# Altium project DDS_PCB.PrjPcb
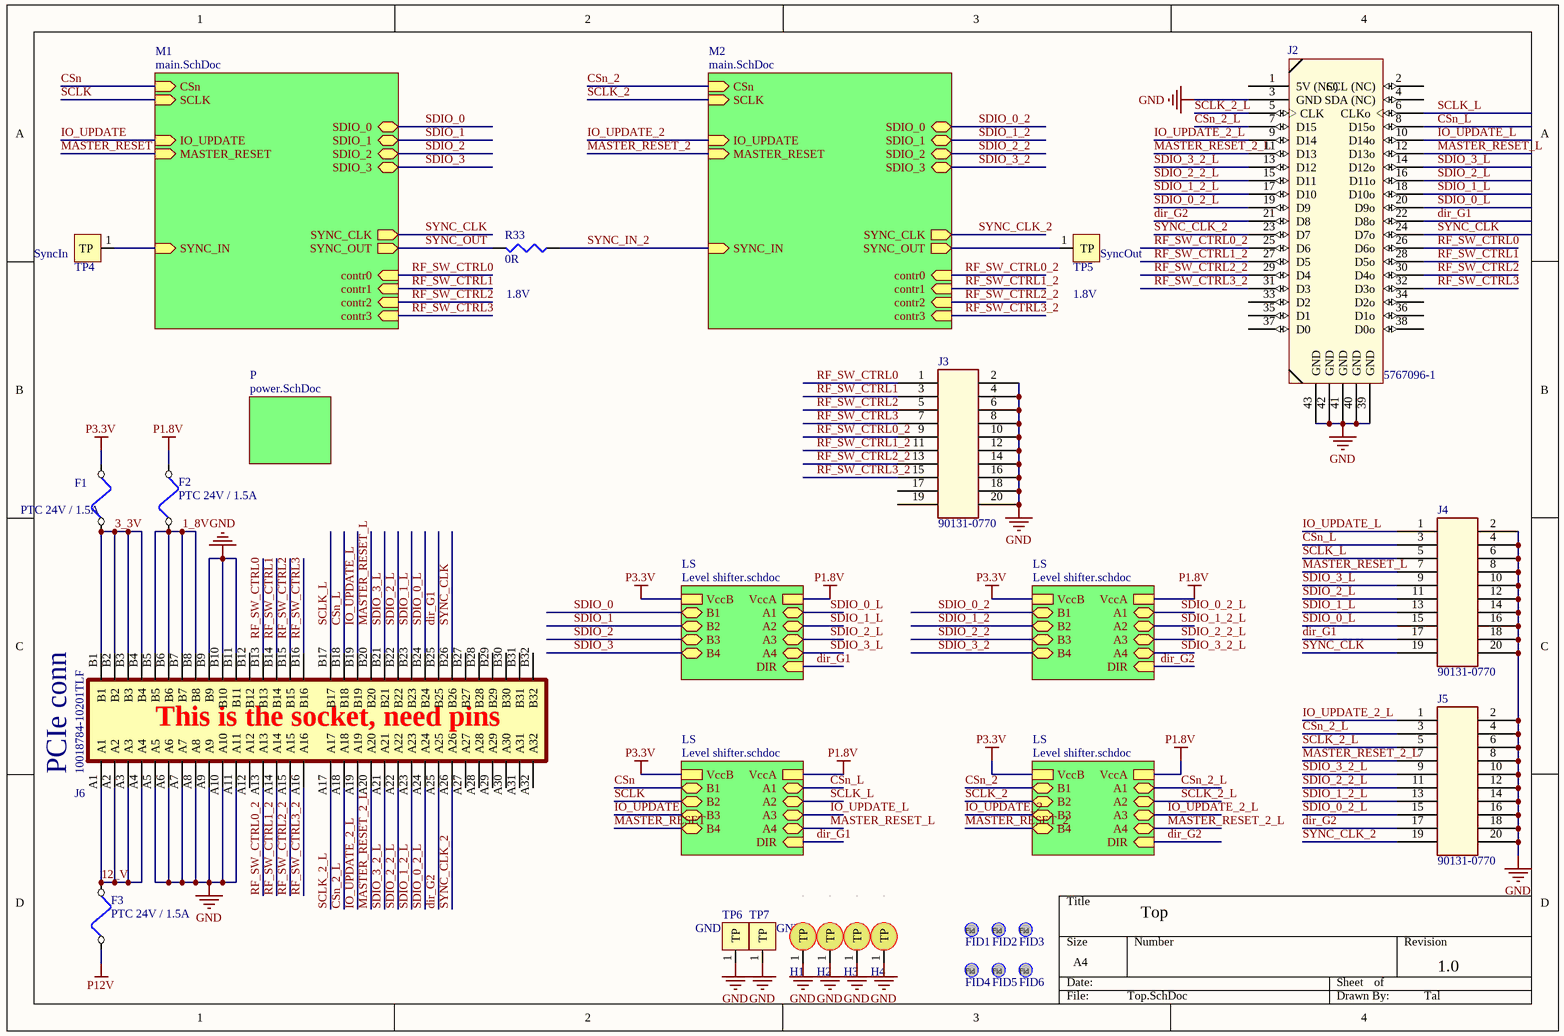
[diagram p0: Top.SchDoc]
6 sheets, 434 parts. Net scope: hierarchical (ports join the sheet entries above them; power ports are global).
Board file: DDS_PCB.PcbDoc
Sheets:
  Top.SchDoc
    M1 = main.SchDoc
      A0 = analog_channel.SchDoc
      A1 = analog_channel.SchDoc
      B0 = analog_channel3.SchDoc
      B1 = analog_channel3.SchDoc
    P = power.SchDoc
    M2 = main.SchDoc
      A0 = analog_channel.SchDoc
      A1 = analog_channel.SchDoc
      B0 = analog_channel3.SchDoc
      B1 = analog_channel3.SchDoc
    LS = Level Shifter.SchDoc
    LS = Level Shifter.SchDoc
    LS = Level Shifter.SchDoc
    LS = Level Shifter.SchDoc

## Sheet Top.SchDoc
size A4; SheetNumber: 1; SheetTotal: 6

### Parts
F1  PTC 24V / 1.5A  [1812_F]
F2  PTC 24V / 1.5A  [1812_F]
F3  PTC 24V / 1.5A  [1812_F]
FID1  Fiducial  [Fiducial]  (value not drawn)
FID2  Fiducial  [Fiducial]  (value not drawn)
FID3  Fiducial  [Fiducial]  (value not drawn)
FID4  Fiducial  [Fiducial]  (value not drawn)
FID5  Fiducial  [Fiducial]  (value not drawn)
FID6  Fiducial  [Fiducial]  (value not drawn)
H1  Hole 3mm  [hole 3mm]  (value not drawn)
H2  Hole 3mm  [hole 3mm]  (value not drawn)
H3  Hole 3mm  [hole 3mm]  (value not drawn)
H4  Hole 3mm  [hole 3mm]  (value not drawn)
J2  5767096-1  [MICTOR-38_PIN]
J3  90131-0770  [HEADER_10x2]
J4  90131-0770  [HEADER_10x2]
J5  90131-0770  [HEADER_10x2]
J6  10018784-10201TLF  [PCIE_8LANE_EDGE]
R33  0R  [R0402]
TP4  SyncIn  [TP_2x1.8]
TP5  SyncOut  [TP_2x1.8]
TP6  GND  [TP_2x1.8]
TP7  GND  [TP_2x1.8]

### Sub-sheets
LS = Level shifter.schdoc: A4 (bidir), B3 (bidir), A2 (bidir), B1 (bidir), B4 (bidir), A1 (bidir), B2 (bidir), A3 (bidir), VccA, VccB, DIR (in)
LS = Level shifter.schdoc: A4 (bidir), B3 (bidir), A2 (bidir), B1 (bidir), B4 (bidir), A1 (bidir), B2 (bidir), A3 (bidir), VccA, VccB, DIR (in)
LS = Level shifter.schdoc: A4 (bidir), B3 (bidir), A2 (bidir), B1 (bidir), B4 (bidir), A1 (bidir), B2 (bidir), A3 (bidir), VccA, VccB, DIR (in)
LS = Level shifter.schdoc: A4 (bidir), B3 (bidir), A2 (bidir), B1 (bidir), B4 (bidir), A1 (bidir), B2 (bidir), A3 (bidir), VccA, VccB, DIR (in)
M1 = main.SchDoc: SYNC_CLK (out), SYNC_OUT (out), SDIO_0 (bidir), SDIO_1 (bidir), SDIO_2 (bidir), SDIO_3 (bidir), CSn (in), IO_UPDATE (in), MASTER_RESET (in), SCLK (in), SYNC_IN (in), contr0 (in), contr1 (in), contr2 (in), contr3 (in)
M2 = main.SchDoc: SYNC_CLK (out), SYNC_OUT (out), SDIO_0 (bidir), SDIO_1 (bidir), SDIO_2 (bidir), SDIO_3 (bidir), CSn (in), IO_UPDATE (in), MASTER_RESET (in), SCLK (in), SYNC_IN (in), contr0 (in), contr1 (in), contr2 (in), contr3 (in)
P = power.SchDoc: no entries

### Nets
GND: H1.1(TP) H2.1(TP) H3.1(TP) H4.1(TP) J2.3(GND) J2.39(GND) J2.40(GND) J2.41(GND) J2.42(GND) J2.43(GND) J3.2 J3.4 J3.6 J3.8 J3.10 J3.12 J3.14 J3.16 J3.18 J3.20 J4.2 J4.4 J4.6 J4.8 J4.10 J4.12 J4.14 J4.16 J4.18 J4.20 J5.2 J5.4 J5.6 J5.8 J5.10 J5.12 J5.14 J5.16 J5.18 J5.20 J6.A5 J6.A6 J6.A7 J6.A8 J6.A9 J6.A10 J6.A11 J6.B9 J6.B10 J6.B11 TP6.1(TP) TP7.1(TP)
P1.8V: F2.2 ; sheet LS/VccA, sheet LS/VccA, sheet LS/VccA, sheet LS/VccA  [project net VccA]
P3.3V: F1.2 ; sheet LS/VccB, sheet LS/VccB, sheet LS/VccB, sheet LS/VccB  [project net VccB]
P12V: F3.1
1_8V: F2.1 J6.B5 J6.B6 J6.B7 J6.B8
3_3V: F1.1 J6.B1 J6.B2 J6.B3 J6.B4
12_V: F3.2 J6.A1 J6.A2 J6.A3 J6.A4
CSn: sheet M1/CSn, sheet LS/B1
CSn_2: sheet M2/CSn, sheet LS/B1
CSn_2_L: J2.7(D15) J5.3 J6.A18 ; sheet LS/A1
CSn_L: J2.8(D15o) J4.3 J6.B18 ; sheet LS/A1
dir_G1: J2.22(D8o) J4.17 J6.B25 ; sheet LS/DIR, sheet LS/DIR  [project net DIR]
dir_G2: J2.21(D8) J5.17 J6.A25 ; sheet LS/DIR, sheet LS/DIR  [project net DIR]
IO_UPDATE: sheet M1/IO_UPDATE, sheet LS/B3
IO_UPDATE_2: sheet M2/IO_UPDATE, sheet LS/B3
IO_UPDATE_2_L: J2.9(D14) J5.1 J6.A19 ; sheet LS/A3
IO_UPDATE_L: J2.10(D14o) J4.1 J6.B19 ; sheet LS/A3
MASTER_RESET: sheet M1/MASTER_RESET, sheet LS/B4
MASTER_RESET_2: sheet M2/MASTER_RESET, sheet LS/B4
MASTER_RESET_2_L: J2.11(D13) J5.7 J6.A20 ; sheet LS/A4
MASTER_RESET_L: J2.12(D13o) J4.7 J6.B20 ; sheet LS/A4
RF_SW_CTRL0: J2.26(D6o) J3.1 J6.B13 ; sheet M1/contr0  [project net contr0]
RF_SW_CTRL0_2: J2.25(D6) J3.9 J6.A13 ; sheet M2/contr0  [project net contr0]
RF_SW_CTRL1: J2.28(D5o) J3.3 J6.B14 ; sheet M1/contr1  [project net contr1]
RF_SW_CTRL1_2: J2.27(D5) J3.11 J6.A14 ; sheet M2/contr1  [project net contr1]
RF_SW_CTRL2: J2.30(D4o) J3.5 J6.B15 ; sheet M1/contr2  [project net contr2]
RF_SW_CTRL2_2: J2.29(D4) J3.13 J6.A15 ; sheet M2/contr2  [project net contr2]
RF_SW_CTRL3: J2.32(D3o) J3.7 J6.B16 ; sheet M1/contr3  [project net contr3]
RF_SW_CTRL3_2: J2.31(D3) J3.15 J6.A16 ; sheet M2/contr3  [project net contr3]
SCLK: sheet M1/SCLK, sheet LS/B2
SCLK_2: sheet M2/SCLK, sheet LS/B2
SCLK_2_L: J2.5(CLK) J5.5 J6.A17 ; sheet LS/A2
SCLK_L: J2.6(CLKo) J4.5 J6.B17 ; sheet LS/A2
SDIO_0: sheet M1/SDIO_0, sheet LS/B1
SDIO_0_2: sheet M2/SDIO_0, sheet LS/B1
SDIO_0_2_L: J2.19(D9) J5.15 J6.A24 ; sheet LS/A1
SDIO_0_L: J2.20(D9o) J4.15 J6.B24 ; sheet LS/A1
SDIO_1: sheet M1/SDIO_1, sheet LS/B2
SDIO_1_2: sheet M2/SDIO_1, sheet LS/B2
SDIO_1_2_L: J2.17(D10) J5.13 J6.A23 ; sheet LS/A2
SDIO_1_L: J2.18(D10o) J4.13 J6.B23 ; sheet LS/A2
SDIO_2: sheet M1/SDIO_2, sheet LS/B3
SDIO_2_2: sheet M2/SDIO_2, sheet LS/B3
SDIO_2_2_L: J2.15(D11) J5.11 J6.A22 ; sheet LS/A3
SDIO_2_L: J2.16(D11o) J4.11 J6.B22 ; sheet LS/A3
SDIO_3: sheet M1/SDIO_3, sheet LS/B4
SDIO_3_2: sheet M2/SDIO_3, sheet LS/B4
SDIO_3_2_L: J2.13(D12) J5.9 J6.A21 ; sheet LS/A4
SDIO_3_L: J2.14(D12o) J4.9 J6.B21 ; sheet LS/A4
SYNC_CLK: J2.24(D7o) J4.19 J6.B26 ; sheet M1/SYNC_CLK
SYNC_CLK_2: J2.23(D7) J5.19 J6.A26 ; sheet M2/SYNC_CLK
SYNC_IN: TP4.1(TP) ; sheet M1/SYNC_IN
SYNC_IN_2: R33.1 ; sheet M2/SYNC_IN
SYNC_OUT: TP5.1(TP) ; sheet M2/SYNC_OUT
SYNC_OUT: R33.2 ; sheet M1/SYNC_OUT  [a separate net that carries the same name]

Not connected (* = marked no-connect by the designer): J2 1(5V_(NC)) 2(SCL_(NC)) 4(SDA_(NC)) 33(D2) 34(D2o) 35(D1) 36(D1o) 37(D0) 38(D0o); J3 17 19; J6 A12 A27 A28 A29 A30 A31 A32 B12 B27 B28 B29 B30 B31 B32

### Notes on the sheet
- (near R33) 1.8V
- (near TP5) 1.8V
- (near J6) PCIe conn
- (near J6) This is the socket, need pins
- Top
- 1.0
- Tal

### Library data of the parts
F1-F3 = 1812L150/24MR: FUSE PTC 24V 1.5A POLYFUSE 1812; Manufacturer: Littelfuse Inc; LANDA P/N: EFS-000011
FID1-FID6 = Fiducial: Assembly: NA
J2 = 5767096-1: CONN MICTOR 38POS .025 VERT SMD; Manufacturer: TE Connectivity; LANDA P/N: ECN-000060
J3-J5 = 90131-0770: CONN HEADER 20 TH; Manufacturer: Molex Connector Corporation; LANDA P/N: ECN-000005
J6 = 10018784-10201TLF: 64 Position Female Connector PCI Expressâ„¢ Gold 0.039 _1.00mm_ Black; MF: Amphenol ICC
R33 = RES 100 OHM 1/10W 1% 0402 SMD: RES 0 OHM 1/10W 1% 0402 SMD; Manufacturer Part Number: ERJ-2RKF1000X; Manufacturer: Panasonic Electronic Components; LANDA P/N: ERS-000079; Assembly: N.C
TP4-TP6 = TP mini_2: TP PC MINIATURE SMT; Manufacturer: Keystone Electronics; Manufacturer Part Number: 5015; Assembly: N.A; LANDA P/N: ECN-000032
TP7 = TP mini_1: TP PC MINIATURE SMT; Manufacturer: Keystone Electronics; Manufacturer Part Number: 5015; Assembly: N.A; LANDA P/N: ECN-000032

## Sheet main.SchDoc
size A4; SheetNumber: 2; SheetTotal: 6; SPICEModelCacheQOCYWOGJ: <root> / <DocumentId>QOCYWOGJ</DocumentId> / </root>
Used 2 times, as channels M1, M2. Parts and nets are listed once, with the designators drawn on the sheet.
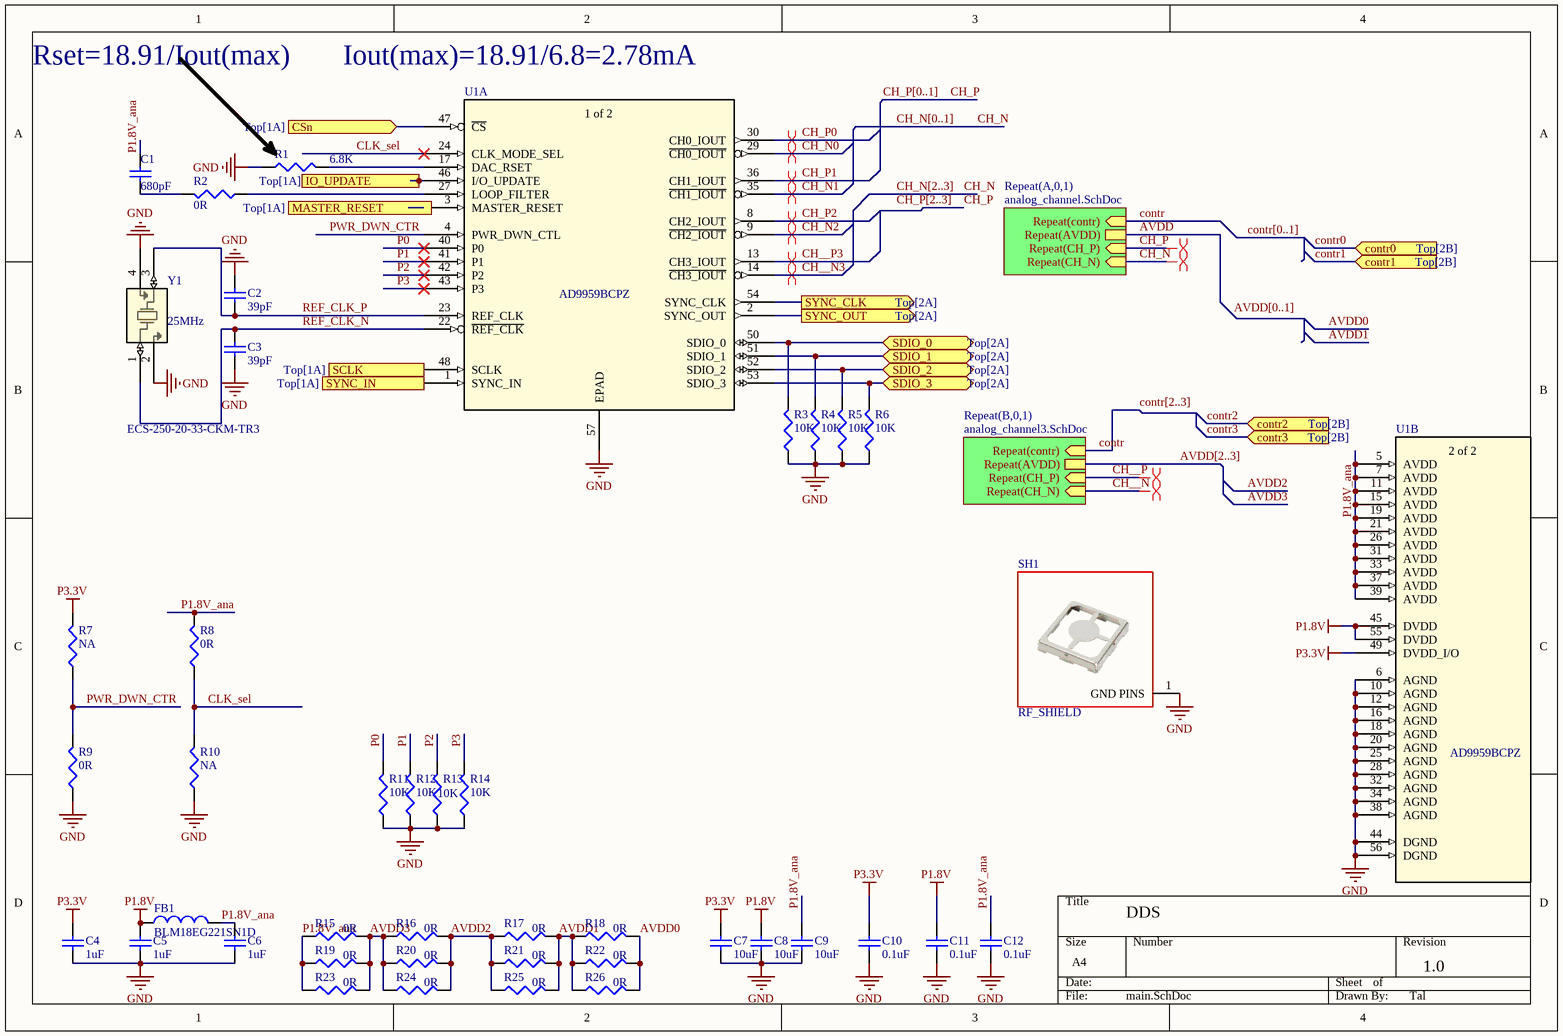
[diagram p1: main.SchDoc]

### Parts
C1  Capacitance: 680pF  [C0402]  (hidden comment: 680pF 50V)
C2  Capacitance: 39pF  [C0402]  (hidden comment: 39pF 50V)
C3  Capacitance: 39pF  [C0402]  (hidden comment: 39pF 50V)
C4  Capacitance: 1uF  [C0402]  (hidden comment: 1uF 25V)
C5  Capacitance: 1uF  [C0402]  (hidden comment: 1uF 25V)
C6  Capacitance: 1uF  [C0402]  (hidden comment: 1uF 25V)
C7  Capacitance: 10uF  [C0402]  (hidden comment: 10uF 10V)
C8  Capacitance: 10uF  [C0402]  (hidden comment: 10uF 10V)
C9  Capacitance: 10uF  [C0402]  (hidden comment: 10uF 10V)
C10  Capacitance: 0.1uF  [C0402]  (hidden comment: 0.1uF 50V)
C11  Capacitance: 0.1uF  [C0402]  (hidden comment: 0.1uF 50V)
C12  Capacitance: 0.1uF  [C0402]  (hidden comment: 0.1uF 50V)
FB1  BLM18EG221SN1D  [fb0603]
R1  6.8K  [R0402]
R2  0R  [R0402]
R3  10K  [R0402]
R4  10K  [R0402]
R5  10K  [R0402]
R6  10K  [R0402]
R7  NA  [R0402]
R8  0R  [R0402]
R9  0R  [R0402]
R10  NA  [R0402]
R11  10K  [R0402]
R12  10K  [R0402]
R13  10K  [R0402]
R14  10K  [R0402]
R15  0R  [R0805]
R16  0R  [R0805]
R17  0R  [R0805]
R18  0R  [R0805]
R19  0R  [R0805]
R20  0R  [R0805]
R21  0R  [R0805]
R22  0R  [R0805]
R23  0R  [R0805]
R24  0R  [R0805]
R25  0R  [R0805]
R26  0R  [R0805]
SH1  RF_SHIELD  [SMS201F]
U1  AD9959BCPZ  [CP_56_1_ADI]  (parts A,B of 2)
Y1  ECS-250-20-33-CKM-TR3  [SMD4_ECX-32_3p2x2p5_ECS]

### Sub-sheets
Repeat(A,0,1) = analog_channel.SchDoc: Repeat(contr) (in), Repeat(AVDD), Repeat(CH_P) (in), Repeat(CH_N) (in)
Repeat(B,0,1) = analog_channel3.SchDoc: Repeat(contr) (in), Repeat(AVDD), Repeat(CH_P) (in), Repeat(CH_N) (in)

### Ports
contr0 (in, see Top[2B]), contr1 (in, see Top[2B]), contr2 (in, see Top[2B]), contr3 (in, see Top[2B]), CSn (in, see Top[1A]), IO_UPDATE (in, see Top[1A]), MASTER_RESET (in, see Top[1A]), SCLK (in, see Top[1A]), SDIO_0 (bidir, see Top[2A]), SDIO_1 (bidir, see Top[2A]), SDIO_2 (bidir, see Top[2A]), SDIO_3 (bidir, see Top[2A]), SYNC_CLK (out, see Top[2A]), SYNC_IN (in, see Top[1A]), SYNC_OUT (out, see Top[2A])

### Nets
GND: C2.2 C3.1 C4.1 C5.1 C6.1 C7.1 C8.1 C9.1 C10.1 C11.1 C12.1 R1.1 R3.1 R4.1 R5.1 R6.1 R9.1 R10.1 R11.1 R12.1 R13.1 R14.1 SH1.1(GND_PINS) U1.6(AGND) U1.10(AGND) U1.12(AGND) U1.16(AGND) U1.18(AGND) U1.20(AGND) U1.25(AGND) U1.28(AGND) U1.32(AGND) U1.34(AGND) U1.38(AGND) U1.44(DGND) U1.56(DGND) U1.57(EPAD) Y1.2 Y1.4
P1.8V: C5.2 C8.2 C11.2 FB1.1 U1.45(DVDD) U1.55(DVDD)
P3.3V: C4.2 C7.2 C10.2 R7.2 U1.49(DVDD_I/O)
AVDD0: R18.2 R22.2 R26.2
AVDD1: R17.2 R18.1 R21.2 R22.1 R25.2 R26.1
AVDD2: R16.2 R17.1 R20.2 R21.1 R24.2 R25.1
AVDD3: R15.2 R16.1 R19.2 R20.1 R23.2 R24.1
CH__N3: U1.14(~{CH3_IOUT})
CH__P3: U1.13(CH3_IOUT)
CH_N0: U1.29(~{CH0_IOUT})
CH_N1: U1.35(~{CH1_IOUT})
CH_N2: U1.9(~{CH2_IOUT})
CH_P0: U1.30(CH0_IOUT)
CH_P1: U1.36(CH1_IOUT)
CH_P2: U1.8(CH2_IOUT)
CLK_sel: R8.1 R10.2 U1.24(CLK_MODE_SEL)
contr: sheet Repeat(A,0,1)/Repeat(contr), sheet Repeat(B,0,1)/Repeat(contr)  [also labelled contr[2..3]]
CSn: U1.47(~{CS}) ; port CSn
IO_UPDATE: U1.46(I/O_UPDATE) ; port IO_UPDATE
P0: R11.2 U1.40(P0)
P1: R12.2 U1.41(P1)
P1.8V_ana: C1.1 C6.2 C9.2 C12.2 FB1.2 R8.2 R15.1 R19.1 R23.1 U1.5(AVDD) U1.7(AVDD) U1.11(AVDD) U1.15(AVDD) U1.19(AVDD) U1.21(AVDD) U1.26(AVDD) U1.31(AVDD) U1.33(AVDD) U1.37(AVDD) U1.39(AVDD)
P2: R13.2 U1.42(P2)
P3: R14.2 U1.43(P3)
PWR_DWN_CTR: R7.1 R9.2 U1.4(PWR_DWN_CTL)
REF_CLK_N: C3.2 U1.22(~{REF_CLK}) Y1.1
REF_CLK_P: C2.1 U1.23(REF_CLK) Y1.3
SCLK: U1.48(SCLK) ; port SCLK
SDIO_0: R3.2 U1.50(SDIO_0) ; port SDIO_0
SDIO_1: R4.2 U1.51(SDIO_1) ; port SDIO_1
SDIO_2: R5.2 U1.52(SDIO_2) ; port SDIO_2
SDIO_3: R6.2 U1.53(SDIO_3) ; port SDIO_3
SYNC_CLK: U1.54(SYNC_CLK) ; port SYNC_CLK
SYNC_IN: U1.1(SYNC_IN) ; port SYNC_IN
SYNC_OUT: U1.2(SYNC_OUT) ; port SYNC_OUT
NetC1_2: C1.2 R2.2
NetR1_2: R1.2 U1.17(DAC_RSET)
NetR2_1: R2.1 U1.27(LOOP_FILTER)

Not connected (* = marked no-connect by the designer): U1 3(MASTER_RESET)

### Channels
M1: designators end in _M1; ports contr0=contr0 contr1=contr1 contr2=contr2 contr3=contr3 CSn=CSn IO_UPDATE=IO_UPDATE MASTER_RESET=MASTER_RESET SCLK=SCLK SDIO_0=SDIO_0 SDIO_1=SDIO_1 SDIO_2=SDIO_2 SDIO_3=SDIO_3 SYNC_CLK=SYNC_CLK SYNC_IN=SYNC_IN SYNC_OUT=SYNC_OUT
M2: designators end in _M2; ports contr0=contr0 contr1=contr1 contr2=contr2 contr3=contr3 CSn=CSn_2 IO_UPDATE=IO_UPDATE_2 MASTER_RESET=MASTER_RESET_2 SCLK=SCLK_2 SDIO_0=SDIO_0_2 SDIO_1=SDIO_1_2 SDIO_2=SDIO_2_2 SDIO_3=SDIO_3_2 SYNC_CLK=SYNC_CLK_2 SYNC_IN=SYNC_IN_2 SYNC_OUT=SYNC_OUT

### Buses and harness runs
bus AVDD[0..1]
bus CH_N[0..1]
bus CH_N[2..3]
bus CH_P[0..1]
bus CH_P[2..3]
bus contr[0..1]

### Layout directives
differential pair: CH__N3_M1, CH__N_M1, CH__P3_M1, CH__P_M1, CH_N, CH_N2_M1, CH_N_M1, CH_P, CH_P2_M1, CH_P_M1

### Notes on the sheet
- Rset=18.91/Iout(max)
- Iout(max)=18.91/6.8=2.78mA
- (near Y1) 25MHz
- DDS
- 1.0
- Tal
- Labels drawn without touching a wire or pin: CH_P[2..3]

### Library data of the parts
C1 = CAP CER 6.8pF 50V NP0 0402: CAP CER 680PF 50V NP0 0402; Manufacturer Part Number: C1005C0G1H6R8D; Manufacturer: TDK Corporation; LANDA P/N: ECP-000033
C2 C3 = CAP CER 6.8pF 50V NP0 0402: CAP CER 39PF 50V NP0 0402; Manufacturer Part Number: C1005C0G1H6R8D; Manufacturer: TDK Corporation; LANDA P/N: ECP-000033
C4-C6 = CAP CER 6.8pF 50V NP0 0402: CAP CER 1uF 25V X5R 0402; Manufacturer Part Number: C1005C0G1H6R8D; Manufacturer: TDK Corporation; LANDA P/N: ECP-000033; Voltage - Rated: 50V
C7-C9 = CAP CER 6.8pF 50V NP0 0402: CAP CER 10uF 10V X5R 0402; Manufacturer Part Number: C1005C0G1H6R8D; Manufacturer: TDK Corporation; LANDA P/N: ECP-000033; Voltage - Rated: 50V
C10-C12 = CAP CER 6.8pF 50V NP0 0402: CAP CER 0.1uF 50V NP0 0402; Manufacturer Part Number: C1005C0G1H6R8D; Manufacturer: TDK Corporation; LANDA P/N: ECP-000033
FB1 = BK1608HS600-T: FERRITE BEAD 220_OHM@100MHz 0603 2A 50mohm_DC; Manufacturer: Taiyo Yuden; LANDA P/N: EIN-000010
R1 = RES 3.09K OHM 1/16W 1% 0402: RES 6.8K OHM 1/16W 1% 0402; Manufacturer Part Number: RMCF0402FT3K09; Manufacturer: Stackpole Electronics Inc; Power (Watts): 0.063W, 1/16W; LANDA P/N: ERS-000063
R2 R7-R10 = RES 100 OHM 1/10W 1% 0402 SMD: as R33 on sheet Top
R3-R6 R11-R14 = RES 3.09K OHM 1/16W 1% 0402: RES 10K OHM 1/16W 1% 0402; Manufacturer Part Number: RMCF0402FT3K09; Manufacturer: Stackpole Electronics Inc; Power (Watts): 0.063W, 1/16W; LANDA P/N: ERS-000063
R15-R26 = RES 200 OHM 1/8W 1% 0805 SMD: RES 0 OHM 1/8W 1% 0805 SMD; Manufacturer Part Number: RMCF0805FT200R; Manufacturer: Stackpole Electronics Inc; Power (Watts): 0.125W, 1/8W; LANDA P/N: ERS-000050
SH1 = RF_SHIELD: RF SHIELD 0.5" X 0.538" SMD; Manufacturer_Part_Number: SMS-201F; Manufacturer: Leader Tech Inc.
U1 = AD9959BCPZ: No Description Available; Mfr_Name: Analog Devices Inc
Y1 = ECS-250-20-33-CKM-TR3: No Description Available; Mfr_Name: ECS International

## Sheet analog_channel.SchDoc
size A4; SheetNumber: 3; SheetTotal: 6
Used 4 times, as channels M1/A0, M1/A1, M2/A0, M2/A1. Parts and nets are listed once, with the designators drawn on the sheet.
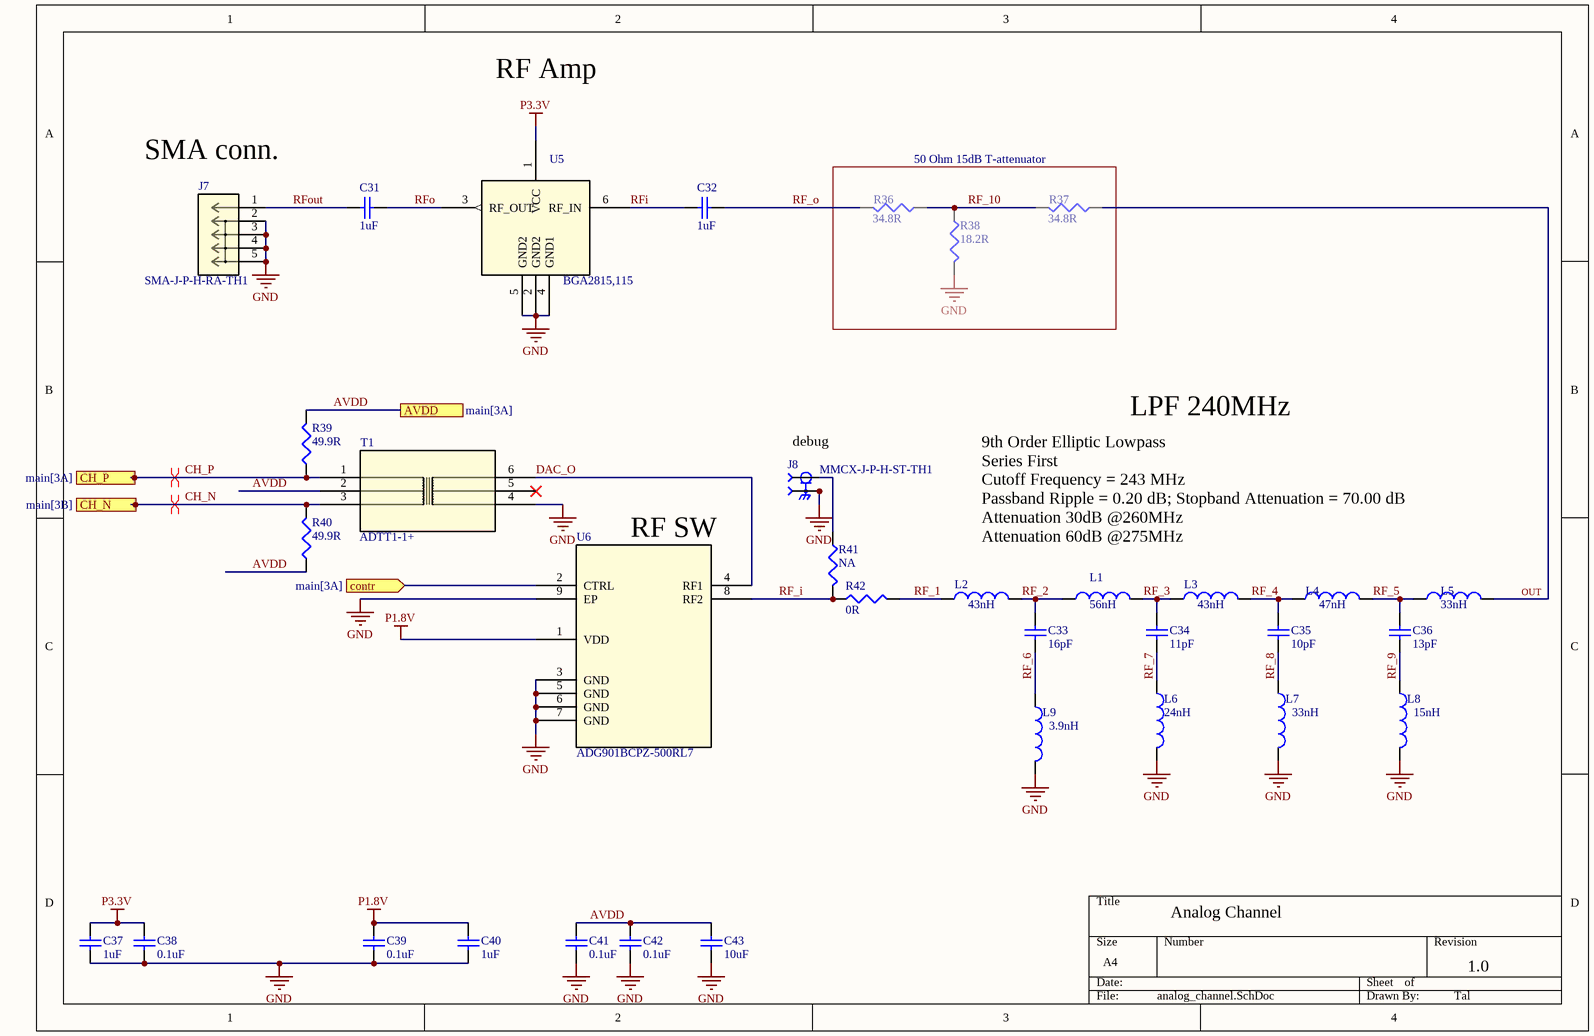
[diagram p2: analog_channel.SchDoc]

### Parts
C31  Capacitance: 1uF  [C0402]  (hidden comment: 1uF 25V)
C32  Capacitance: 1uF  [C0402]  (hidden comment: 1uF 25V)
C33  Capacitance: 16pF  [C0402]  (hidden comment: 16pF 50V)
C34  Capacitance: 11pF  [C0402]  (hidden comment: 11pF 50V)
C35  Capacitance: 10pF  [C0402]  (hidden comment: 10pF 50V)
C36  Capacitance: 13pF  [C0402]  (hidden comment: 13pF 50V)
C37  Capacitance: 1uF  [C0402]  (hidden comment: 1uF 25V)
C38  Capacitance: 0.1uF  [C0402]  (hidden comment: 0.1uF 50V)
C39  Capacitance: 0.1uF  [C0402]  (hidden comment: 0.1uF 50V)
C40  Capacitance: 1uF  [C0402]  (hidden comment: 1uF 25V)
C41  Capacitance: 0.1uF  [C0402]  (hidden comment: 0.1uF 50V)
C42  Capacitance: 0.1uF  [C0402]  (hidden comment: 0.1uF 50V)
C43  Capacitance: 10uF  [C0402]  (hidden comment: 10uF 10V)
J7  SMA-J-P-H-RA-TH1  [CONN_SMA-J-P-H-RA-TH1_SAI]
J8  MMCX-J-P-H-ST-TH1  [SAMTEC_MMCX-J-P-H-ST-TH1]
L1  value 56nH  [0402-A]  (hidden comment: Inductor)
L2  value 43nH  [0402-A]  (hidden comment: Inductor)
L3  value 43nH  [0402-A]  (hidden comment: Inductor)
L4  value 47nH  [0402-A]  (hidden comment: Inductor)
L5  value 33nH  [0402-A]  (hidden comment: Inductor)
L6  value 24nH  [0402-A]  (hidden comment: Inductor)
L7  value 33nH  [0402-A]  (hidden comment: Inductor)
L8  value 15nH  [0402-A]  (hidden comment: Inductor)
L9  value 3.9nH  [0402-A]  (hidden comment: Inductor)
R36  34.8R  [r0402]
R37  34.8R  [r0402]
R38  18.2R  [r0402]
R39  49.9R  [R0402]
R40  49.9R  [R0402]
R41  NA  [r0402]
R42  0R  [r0402]
T1  ADTT1-1+  [CD542_MNC]
U5  BGA2815,115  [SOT_2815,115_NXP]
U6  ADG901BCPZ-500RL7  [CP_8_2_ADI]

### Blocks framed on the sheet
50 Ohm 15dB T-attenuator: R36-R38

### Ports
AVDD (see main[3A]), CH_N (in, see main[3B]), CH_P (in, see main[3A]), contr (in, see main[3A])

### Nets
GND: C37.1 C38.1 C39.1 C40.1 C41.1 C42.1 C43.1 J7.2 J7.3 J7.4 J7.5 J8.S1 J8.S2 J8.S3 J8.S4 L6.2 L7.2 L8.2 L9.2 R38.2 T1.4 U5.2(GND2) U5.4(GND1) U5.5(GND2) U6.3(GND) U6.5(GND) U6.6(GND) U6.7(GND) U6.9(EP)
P1.8V: C39.2 C40.2 U6.1(VDD)
P3.3V: C37.2 C38.2 U5.1(VCC)
AVDD: C41.2 C42.2 C43.2 R39.2 R40.1 T1.2 ; port AVDD
CH_N: R40.2 T1.3 ; port CH_N
CH_P: R39.1 T1.1 ; port CH_P
contr: U6.2(CTRL) ; port contr
DAC_O: T1.6 U6.4(RF1)
OUT: L5.2 R37.1
RF_1: L2.1 R42.2
RF_2: C33.1 L1.1 L2.2
RF_3: C34.1 L1.2 L3.1
RF_4: C35.1 L3.2 L4.1
RF_5: C36.1 L4.2 L5.1
RF_6: C33.2 L9.1
RF_7: C34.2 L6.1
RF_8: C35.2 L7.1
RF_9: C36.2 L8.1
RF_10: R36.1 R37.2 R38.1
RF_i: R41.2 R42.1 U6.8(RF2)
RF_o: C32.2 R36.2
RFi: C32.1 U5.6(RF_IN)
RFo: C31.2 U5.3(RF_OUT)
RFout: C31.1 J7.1
NetJ8_1: J8.1 R41.1

Not connected (* = marked no-connect by the designer): T1 5*

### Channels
M1/A0: designators end in _A2; ports AVDD=AVDD CH_N=CH_N CH_P=CH_P contr=contr0
M1/A1: designators end in _A1; ports AVDD=AVDD CH_N=CH_N CH_P=CH_P contr=contr1
M2/A0: designators end in _A4; ports AVDD=AVDD CH_N=CH_N CH_P=CH_P contr=contr0
M2/A1: designators end in _A3; ports AVDD=AVDD CH_N=CH_N CH_P=CH_P contr=contr1

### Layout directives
differential pair: CH_N, CH_P

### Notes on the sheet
- RF Amp
- (near J7) SMA conn.
- (near J8) debug
- LPF 240MHz
- (near U6) RF SW
- 9th Order Elliptic Lowpass
  Series First
  Cutoff Frequency = 243 MHz
  Passband Ripple = 0.20 dB; Stopband Attenuation = 70.00 dB
  Attenuation 30dB @260MHz
  Attenuation 60dB @275MHz
- Analog Channel
- 1.0
- Tal

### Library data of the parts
C31 C32 C37 C40 = CAP CER 6.8pF 50V NP0 0402: as C4 on sheet main
C33 = CAP CER 20pF 50V 5% NP0 0402: CAP CER 16PF 50V 5% NP0 0402; Manufacturer: TDK Corporation; Manufacturer Part Number: C1005C0G1H200J; LANDA P/N: ECP-000034
C34 = CAP CER 20pF 50V 5% NP0 0402: CAP CER 11PF 50V 5% NP0 0402; Manufacturer: TDK Corporation; Manufacturer Part Number: C1005C0G1H200J; LANDA P/N: ECP-000034
C35 = CAP CER 20pF 50V 5% NP0 0402: CAP CER 10PF 50V 5% NP0 0402; Manufacturer: TDK Corporation; Manufacturer Part Number: C1005C0G1H200J; LANDA P/N: ECP-000034
C36 = CAP CER 20pF 50V 5% NP0 0402: CAP CER 13PF 50V 5% NP0 0402; Manufacturer: TDK Corporation; Manufacturer Part Number: C1005C0G1H200J; LANDA P/N: ECP-000034
C38 C39 C41 C42 = CAP CER 6.8pF 50V NP0 0402: as C10 on sheet main
C43 = CAP CER 6.8pF 50V NP0 0402: as C7 on sheet main
J7 = SMA-J-P-H-RA-TH1: No Description Available; Mfr_Name: Samtec Inc
J8 = MMCX-J-P-H-ST-TH1: MMCX STRAIGHT, THROUGH HOLE JACK- 50 OHM; MF: Samtec
L1-L9 = Inductor: Code_IEC: 1005
R36 R37 = RES 100 OHM 1/10W 1% 0402 SMD: RES 34.8 OHM 1/10W 1% 0402 SMD; Manufacturer Part Number: ERJ-2RKF1000X; Manufacturer: Panasonic Electronic Components; LANDA P/N: ERS-000079; Assembly: N.C
R38 = RES 100 OHM 1/10W 1% 0402 SMD: RES 18.2 OHM 1/10W 1% 0402 SMD; Manufacturer Part Number: ERJ-2RKF1000X; Manufacturer: Panasonic Electronic Components; LANDA P/N: ERS-000079; Assembly: N.C
R39 R40 = RES 100 OHM 1/10W 1% 0402 SMD: RES 49.9 OHM 1/10W 1% 0402 SMD; Manufacturer Part Number: ERJ-2RKF1000X; Manufacturer: Panasonic Electronic Components; LANDA P/N: ERS-000079; Assembly: N.C
R41 R42 = RES 100 OHM 1/10W 1% 0402 SMD: as R33 on sheet Top
T1 = ADTT1-1+: No Description Available; Mfr_Name: Mini Circuits; Type: DEV
U5 = BGA2815,115: No Description Available; Mfr_Name: NXP
U6 = ADG901BCPZ-500RL7: No Description Available; Mfr_Name: Analog Devices Inc

## Sheet analog_channel3.SchDoc
size A4; SheetNumber: 4; SheetTotal: 6
Used 4 times, as channels M1/B0, M1/B1, M2/B0, M2/B1. Parts and nets are listed once, with the designators drawn on the sheet.
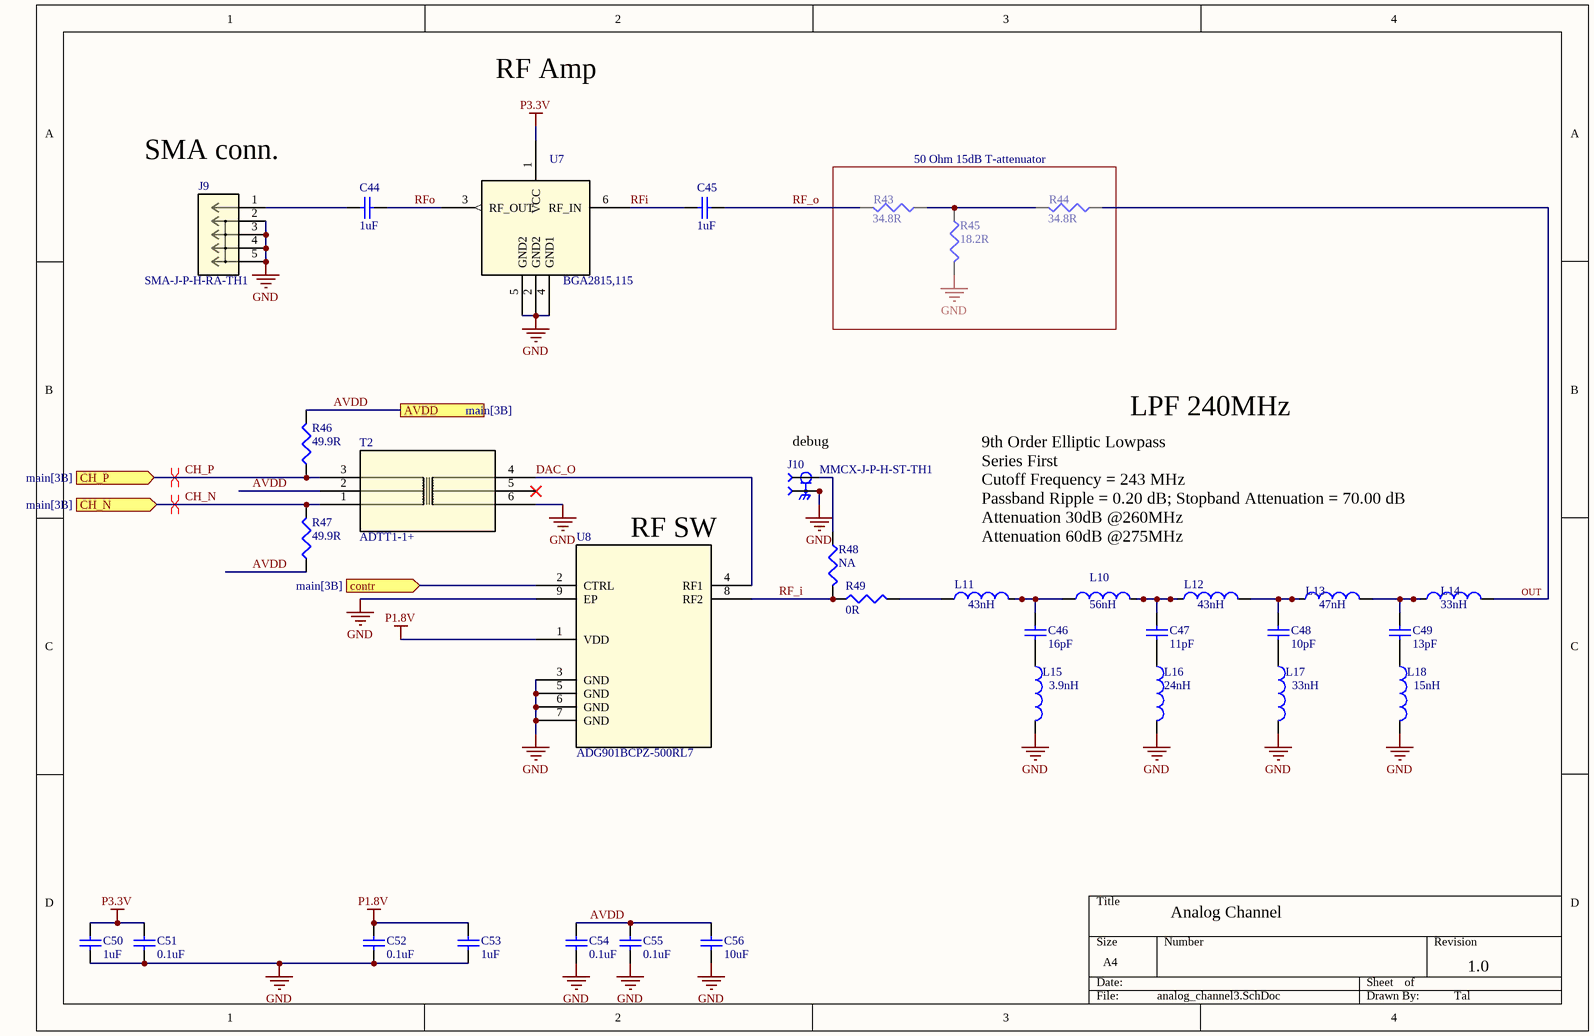
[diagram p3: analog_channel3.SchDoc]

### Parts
C44  Capacitance: 1uF  [C0402]  (hidden comment: 1uF 25V)
C45  Capacitance: 1uF  [C0402]  (hidden comment: 1uF 25V)
C46  Capacitance: 16pF  [C0402]  (hidden comment: 16pF 50V)
C47  Capacitance: 11pF  [C0402]  (hidden comment: 11pF 50V)
C48  Capacitance: 10pF  [C0402]  (hidden comment: 10pF 50V)
C49  Capacitance: 13pF  [C0402]  (hidden comment: 13pF 50V)
C50  Capacitance: 1uF  [C0402]  (hidden comment: 1uF 25V)
C51  Capacitance: 0.1uF  [C0402]  (hidden comment: 0.1uF 50V)
C52  Capacitance: 0.1uF  [C0402]  (hidden comment: 0.1uF 50V)
C53  Capacitance: 1uF  [C0402]  (hidden comment: 1uF 25V)
C54  Capacitance: 0.1uF  [C0402]  (hidden comment: 0.1uF 50V)
C55  Capacitance: 0.1uF  [C0402]  (hidden comment: 0.1uF 50V)
C56  Capacitance: 10uF  [C0402]  (hidden comment: 10uF 10V)
J9  SMA-J-P-H-RA-TH1  [CONN_SMA-J-P-H-RA-TH1_SAI]
J10  MMCX-J-P-H-ST-TH1  [SAMTEC_MMCX-J-P-H-ST-TH1]
L10  value 56nH  [0402-A]  (hidden comment: Inductor)
L11  value 43nH  [0402-A]  (hidden comment: Inductor)
L12  value 43nH  [0402-A]  (hidden comment: Inductor)
L13  value 47nH  [0402-A]  (hidden comment: Inductor)
L14  value 33nH  [0402-A]  (hidden comment: Inductor)
L15  value 3.9nH  [0402-A]  (hidden comment: Inductor)
L16  value 24nH  [0402-A]  (hidden comment: Inductor)
L17  value 33nH  [0402-A]  (hidden comment: Inductor)
L18  value 15nH  [0402-A]  (hidden comment: Inductor)
R43  34.8R  [r0402]
R44  34.8R  [r0402]
R45  18.2R  [r0402]
R46  49.9R  [R0402]
R47  49.9R  [R0402]
R48  NA  [r0402]
R49  0R  [r0402]
T2  ADTT1-1+  [CD542_MNC]
U7  BGA2815,115  [SOT_2815,115_NXP]
U8  ADG901BCPZ-500RL7  [CP_8_2_ADI]

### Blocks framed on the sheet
50 Ohm 15dB T-attenuator: R43-R45

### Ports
AVDD (see main[3B]), CH_N (in, see main[3B]), CH_P (in, see main[3B]), contr (in, see main[3B])

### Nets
GND: C50.1 C51.1 C52.1 C53.1 C54.1 C55.1 C56.1 J9.2 J9.3 J9.4 J9.5 J10.S1 J10.S2 J10.S3 J10.S4 L15.2 L16.2 L17.2 L18.2 R45.2 T2.6 U7.2(GND2) U7.4(GND1) U7.5(GND2) U8.3(GND) U8.5(GND) U8.6(GND) U8.7(GND) U8.9(EP)
P1.8V: C52.2 C53.2 U8.1(VDD)
P3.3V: C50.2 C51.2 U7.1(VCC)
AVDD: C54.2 C55.2 C56.2 R46.2 R47.1 T2.2 ; port AVDD
CH_N: R47.2 T2.1 ; port CH_N
CH_P: R46.1 T2.3 ; port CH_P
contr: U8.2(CTRL) ; port contr
DAC_O: T2.4 U8.4(RF1)
OUT: L14.2 R44.1
RF_i: R48.2 R49.1 U8.8(RF2)
RF_o: C45.2 R43.2
RFi: C45.1 U7.6(RF_IN)
RFo: C44.2 U7.3(RF_OUT)
NetC44_1: C44.1 J9.1
NetC46_1: C46.1 L10.1 L11.2
NetC46_2: C46.2 L15.1
NetC47_1: C47.1 L10.2 L12.1
NetC47_2: C47.2 L16.1
NetC48_1: C48.1 L12.2 L13.1
NetC48_2: C48.2 L17.1
NetC49_1: C49.1 L13.2 L14.1
NetC49_2: C49.2 L18.1
NetJ10_1: J10.1 R48.1
NetL11_1: L11.1 R49.2
NetR43_1: R43.1 R44.2 R45.1

Not connected (* = marked no-connect by the designer): T2 5*

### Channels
M1/B0: designators C44=C44_M1_B0 C45=C45_M1_B0 C46=C46_M1_B0 C47=C47_M1_B0 C48=C48_M1_B0 C49=C49_M1_B0 C50=C50_M1_B0 C51=C51_M1_B0 C52=C52_M1_B0 C53=C53_M1_B0 C54=C54_M1_B0 C55=C55_M1_B0 C56=C56_M1_B0 J9=J9_B2 J10=J10_B2 L10=L10_B2 L11=L11_B2 L12=L12_B2 L13=L13_B2 L14=L14_B2 L15=L15_B2 L16=L16_B2 L17=L17_B2 L18=L18_B2 R43=R43_B2 R44=R44_B2 R45=R45_B2 R46=R46_M1_B0 R47=R47_M1_B0 R48=R48_B2 R49=R49_B2 T2=T2_B2 U7=U7_B2 U8=U8_B2; ports AVDD=AVDD_B0 CH_N=CH__N0_M1 CH_P=CH__P0_M1 contr=contr0
M1/B1: designators C44=C44_M1_B1 C45=C45_M1_B1 C46=C46_M1_B1 C47=C47_M1_B1 C48=C48_M1_B1 C49=C49_M1_B1 C50=C50_M1_B1 C51=C51_M1_B1 C52=C52_M1_B1 C53=C53_M1_B1 C54=C54_M1_B1 C55=C55_M1_B1 C56=C56_M1_B1 J9=J9_B1 J10=J10_B1 L10=L10_B1 L11=L11_B1 L12=L12_B1 L13=L13_B1 L14=L14_B1 L15=L15_B1 L16=L16_B1 L17=L17_B1 L18=L18_B1 R43=R43_B1 R44=R44_B1 R45=R45_B1 R46=R46_M1_B1 R47=R47_M1_B1 R48=R48_B1 R49=R49_B1 T2=T2_B1 U7=U7_B1 U8=U8_B1; ports AVDD=AVDD_B1 CH_N=CH__N1_M1 CH_P=CH__P1_M1 contr=contr1
M2/B0: designators end in _B4; ports AVDD=AVDD_B0 CH_N=CH__N0_M2 CH_P=CH__P0_M2 contr=contr0
M2/B1: designators end in _B3; ports AVDD=AVDD_B1 CH_N=CH__N1_M2 CH_P=CH__P1_M2 contr=contr1

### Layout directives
differential pair: CH__N0_M1, CH__P0_M1

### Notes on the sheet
- RF Amp
- (near J9) SMA conn.
- (near J10) debug
- LPF 240MHz
- (near U8) RF SW
- 9th Order Elliptic Lowpass
  Series First
  Cutoff Frequency = 243 MHz
  Passband Ripple = 0.20 dB; Stopband Attenuation = 70.00 dB
  Attenuation 30dB @260MHz
  Attenuation 60dB @275MHz
- Analog Channel
- 1.0
- Tal

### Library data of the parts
C44 C45 C50 C53 = CAP CER 6.8pF 50V NP0 0402: as C4 on sheet main
C46 = CAP CER 20pF 50V 5% NP0 0402: as C33 on sheet analog_channel
C47 = CAP CER 20pF 50V 5% NP0 0402: as C34 on sheet analog_channel
C48 = CAP CER 20pF 50V 5% NP0 0402: as C35 on sheet analog_channel
C49 = CAP CER 20pF 50V 5% NP0 0402: as C36 on sheet analog_channel
C51 C52 C54 C55 = CAP CER 6.8pF 50V NP0 0402: as C10 on sheet main
C56 = CAP CER 6.8pF 50V NP0 0402: as C7 on sheet main
J9 = SMA-J-P-H-RA-TH1: as J7 on sheet analog_channel
J10 = MMCX-J-P-H-ST-TH1: as J8 on sheet analog_channel
L10-L18 = Inductor: Code_IEC: 1005
R43 R44 = RES 100 OHM 1/10W 1% 0402 SMD: as R36 on sheet analog_channel
R45 = RES 100 OHM 1/10W 1% 0402 SMD: as R38 on sheet analog_channel
R46 R47 = RES 100 OHM 1/10W 1% 0402 SMD: as R39 on sheet analog_channel
R48 R49 = RES 100 OHM 1/10W 1% 0402 SMD: as R33 on sheet Top
T2 = ADTT1-1+: as T1 on sheet analog_channel
U7 = BGA2815,115: No Description Available; Mfr_Name: NXP
U8 = ADG901BCPZ-500RL7: as U6 on sheet analog_channel

## Sheet power.SchDoc
size A4; SheetNumber: 5; SheetTotal: 6
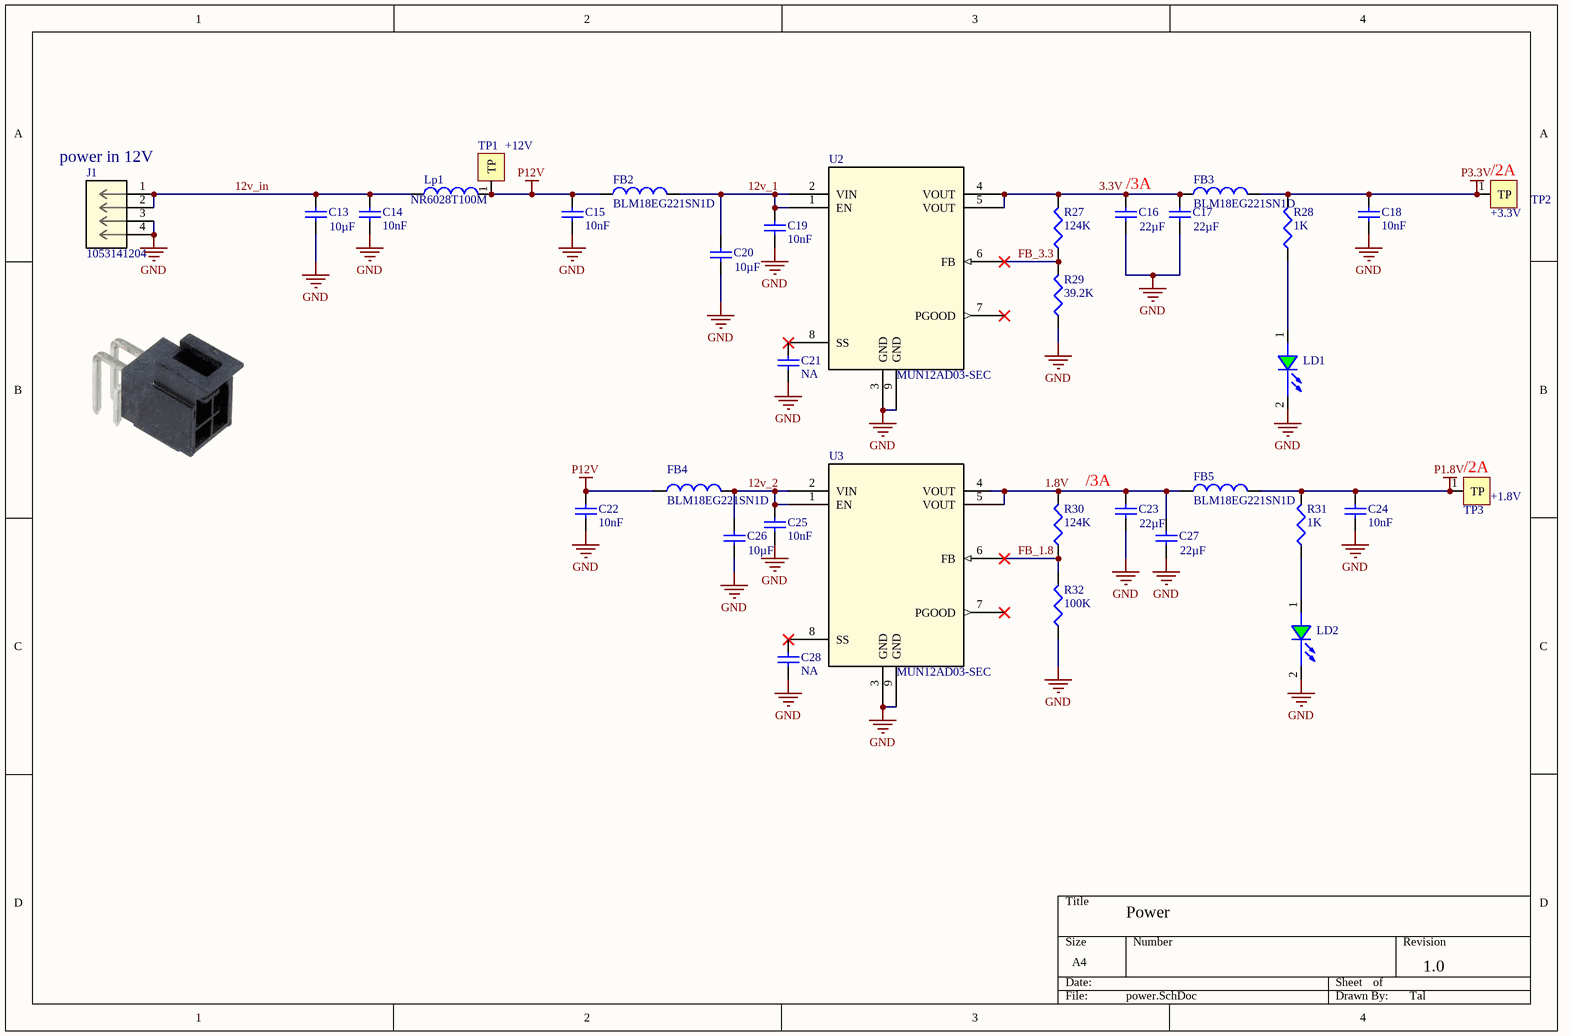
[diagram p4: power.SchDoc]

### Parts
C13  Capacitance: 10µF  [C0603]  (hidden comment: 10uF 25V)
C14  Capacitance: 10nF  [C0402]  (hidden comment: 10nF 25V)
C15  Capacitance: 10nF  [C0402]  (hidden comment: 10nF 25V)
C16  Capacitance: 22µF  [C0603]  (hidden comment: 22uF 16V)
C17  Capacitance: 22µF  [C0603]  (hidden comment: 22uF 16V)
C18  Capacitance: 10nF  [C0402]  (hidden comment: 10nF 25V)
C19  Capacitance: 10nF  [C0402]  (hidden comment: 10nF 25V)
C20  Capacitance: 10µF  [C0603]  (hidden comment: 10uF 25V)
C21  NA  [C0402]
C22  Capacitance: 10nF  [C0402]  (hidden comment: 10nF 25V)
C23  Capacitance: 22µF  [C0603]  (hidden comment: 22uF 16V)
C24  Capacitance: 10nF  [C0402]  (hidden comment: 10nF 25V)
C25  Capacitance: 10nF  [C0402]  (hidden comment: 10nF 25V)
C26  Capacitance: 10µF  [C0603]  (hidden comment: 10uF 25V)
C27  Capacitance: 22µF  [C0603]  (hidden comment: 22uF 16V)
C28  NA  [C0402]
FB2  BLM18EG221SN1D  [fb0603]
FB3  BLM18EG221SN1D  [FB0603]
FB4  BLM18EG221SN1D  [fb0603]
FB5  BLM18EG221SN1D  [fb0603]
J1  1053141204  [CON_1053141204]
LD1  APT1608SGC  [LED_0603_Green]  (value not drawn)
LD2  APT1608SGC  [LED_0603_Green]  (value not drawn)
Lp1  NR6028T100M  [ind6x6_H3]
R27  124K  [R0402]
R28  1K  [R0402]
R29  39.2K  [R0402]
R30  124K  [R0402]
R31  1K  [R0402]
R32  100K  [R0402]
TP1  +12V  [TP_2x1.8]
TP2  +3.3V  [TP_2x1.8]
TP3  +1.8V  [TP_2x1.8]
U2  MUN12AD03-SEC  [SO8_MUN12AD_DEA]
U3  MUN12AD03-SEC  [SO8_MUN12AD_DEA]

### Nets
GND: C13.1 C14.1 C15.1 C16.1 C17.1 C18.1 C19.1 C20.1 C21.1 C22.1 C23.1 C24.1 C25.1 C26.1 C27.1 C28.1 J1.3 J1.4 LD1.2(CATHODE) LD2.2(CATHODE) R29.1 R32.1 U2.3(GND) U2.9(GND) U3.3(GND) U3.9(GND)
P1.8V: C24.2 FB5.2 R31.2 TP3.1(TP)  [project net VccA]
P3.3V: C18.2 FB3.2 R28.2 TP2.1(TP)  [project net VccB]
P12V: C15.2 C22.2 FB2.1 FB4.1 Lp1.2 TP1.1(TP)
1.8V: C23.2 C27.2 FB5.1 R30.2 U3.4(VOUT) U3.5(VOUT)
3.3V: C16.2 C17.2 FB3.1 R27.2 U2.4(VOUT) U2.5(VOUT)
12v_1: C19.2 C20.2 FB2.2 U2.1(EN) U2.2(VIN)
12v_2: C25.2 C26.2 FB4.2 U3.1(EN) U3.2(VIN)
12v_in: C13.2 C14.2 J1.1 J1.2 Lp1.1
FB_1.8: R30.1 R32.2 U3.6(FB)
FB_3.3: R27.1 R29.2 U2.6(FB)
NetC21_2: C21.2 U2.8(SS)
NetC28_2: C28.2 U3.8(SS)
NetLD1_1: LD1.1(ANODE) R28.1
NetLD2_1: LD2.1(ANODE) R31.1

Not connected (* = marked no-connect by the designer): U2 7(PGOOD)*; U3 7(PGOOD)*

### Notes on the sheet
- (near J1) power in 12V
- (near TP2) /2A
- (near C16) /3A
- /3A
- (near TP3) /2A
- Power
- 1.0
- Tal

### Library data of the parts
C13 C20 C26 = CAP CER 10uF 10V 10% X5R 0603: CAP CER 10UF 25V 10% X5R 0603; Manufacturer Part Number: C1608X5R1A106K; Manufacturer: TDK Corporation; LANDA P/N: ECP-000008; Voltage - Rated: 10V
C14 C15 C18 C19 C22 C24 C25 = CAP CER 12nF 25V 10% X7R 0402: CAP CER 10nF 25V 10% X5R 0402; Manufacturer Part Number: GRM155R71E123KA61D; Manufacturer: Murata Electronics North America; LANDA P/N: ECP-000042
C16 C17 C23 C27 = CAP CER 10uF 10V 10% X5R 0603: CAP CER 22UF 16V 10% X5R 0603; Manufacturer Part Number: C1608X5R1A106K; Manufacturer: TDK Corporation; LANDA P/N: ECP-000008; Voltage - Rated: 10V
C21 C28 = CAP CER 6.8pF 50V NP0 0402: CAP CER NA 50V NP0 0402; Manufacturer Part Number: C1005C0G1H6R8D; Manufacturer: TDK Corporation; LANDA P/N: ECP-000033
FB2-FB5 = BK1608HS600-T: as FB1 on sheet main
J1 = 1053141204: No Description Available; Mfr_Name: Molex Connector Corporation
LD1 LD2 = APT1608SGC: LED 1.6X0.8MM 568NM GRN CLR SMD; Manufacturer: Kingbright Corp; LANDA P/N: EDI-000006
Lp1 = NR6028T100M: INDUCTOR 10UH 1.9A 20% SMD; Manufacturer: Taiyo Yuden; Shielding: Shielded; LANDA P/N: EIN-000003
R27 R30 = RES 15.4K OHM 1/10W 1% 0402 SMD: RES 124K OHM 1/10W 1% 0402 SMD; Manufacturer: Panasonic Electronic Components; Manufacturer Part Number: ERJ-2RKF1542X; Power (Watts): 0.1W, 1/10W; LANDA P/N: ERS-000060
R28 R31 = RES 3.09K OHM 1/16W 1% 0402: RES 1K OHM 1/16W 1% 0402; Manufacturer Part Number: RMCF0402FT3K09; Manufacturer: Stackpole Electronics Inc; Power (Watts): 0.063W, 1/16W; LANDA P/N: ERS-000063
R29 = RES 15.4K OHM 1/10W 1% 0402 SMD: RES 39.2K OHM 1/10W 1% 0402 SMD; Manufacturer: Panasonic Electronic Components; Manufacturer Part Number: ERJ-2RKF1542X; Power (Watts): 0.1W, 1/10W; LANDA P/N: ERS-000060
R32 = RES 3.09K OHM 1/16W 1% 0402: RES 100K OHM 1/16W 1% 0402; Manufacturer Part Number: RMCF0402FT3K09; Manufacturer: Stackpole Electronics Inc; Power (Watts): 0.063W, 1/16W; LANDA P/N: ERS-000063
TP1-TP3 = TP mini_2: as TP4 on sheet Top
U2 U3 = MUN12AD03-SEC: No Description Available; Mfr_Name: Delta

## Sheet Level Shifter.SchDoc
size A4; SheetNumber: 6; SheetTotal: 6
Used 4 times, as channels LS, LS, LS, LS. Parts and nets are listed once, with the designators drawn on the sheet.
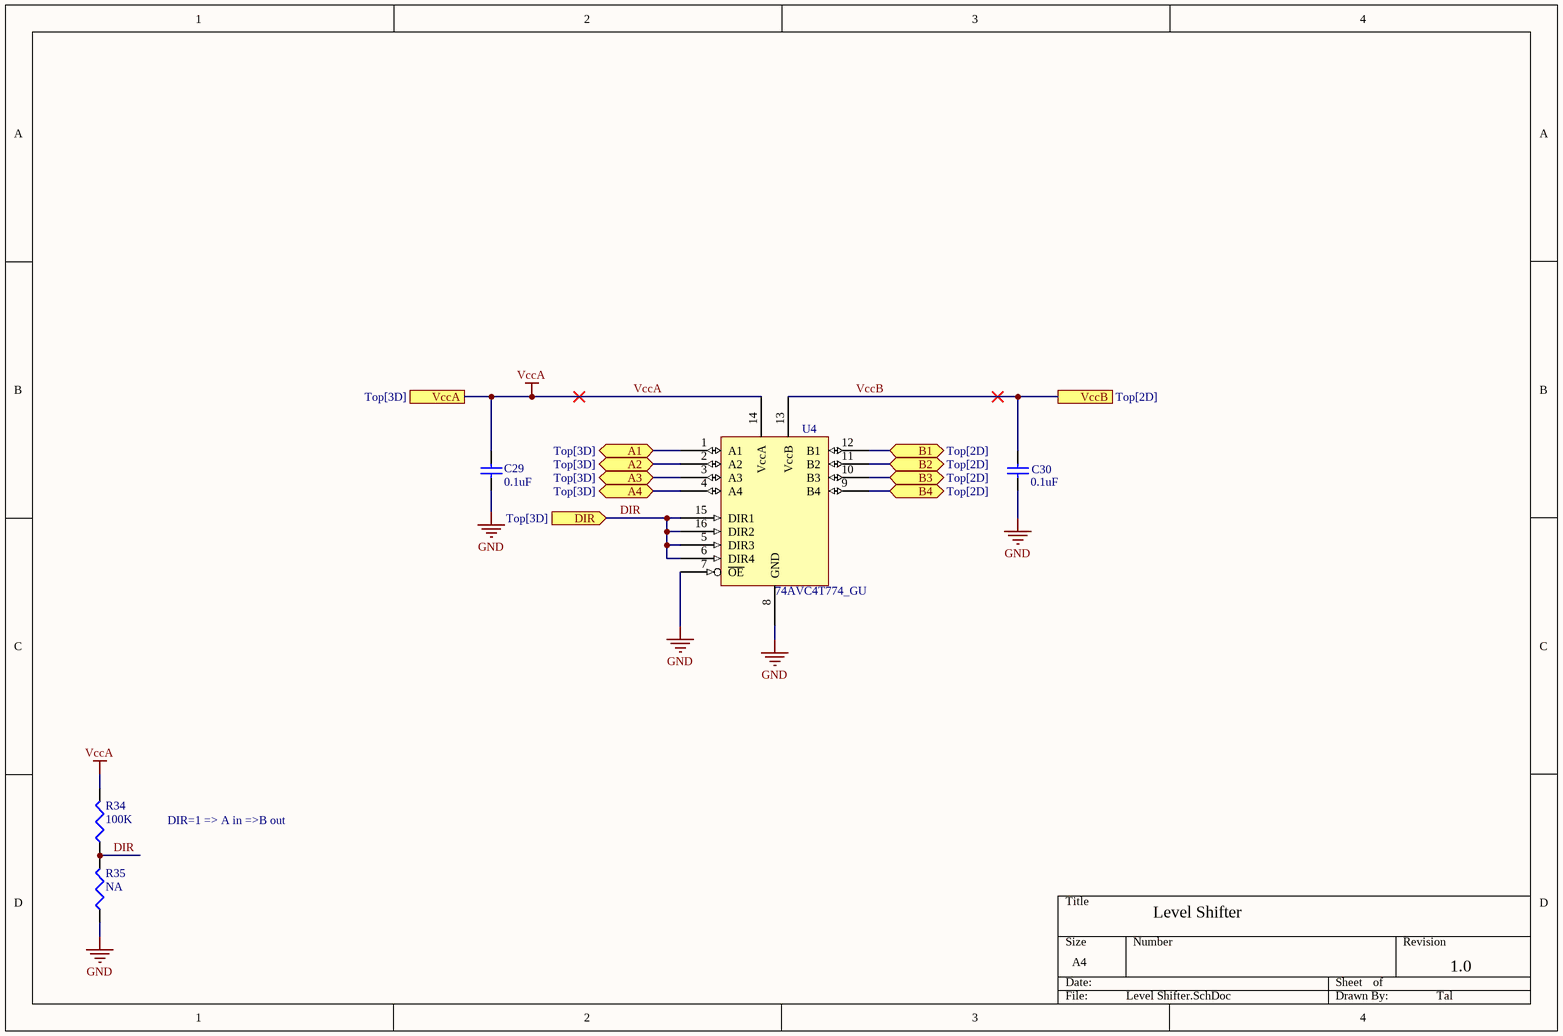
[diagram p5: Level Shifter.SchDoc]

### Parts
C29  Capacitance: 0.1uF  [C0402]  (hidden comment: 0.1uF 50V)
C30  Capacitance: 0.1uF  [C0402]  (hidden comment: 0.1uF 50V)
R34  100K  [R0402]
R35  NA  [R0402]
U4  74AVC4T774_GU  [NXP_74AVC4T245GU,115]

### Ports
A1 (bidir, see Top[3D]), A2 (bidir, see Top[3D]), A3 (bidir, see Top[3D]), A4 (bidir, see Top[3D]), B1 (bidir, see Top[2D]), B2 (bidir, see Top[2D]), B3 (bidir, see Top[2D]), B4 (bidir, see Top[2D]), DIR (in, see Top[3D]), VccA (see Top[3D]), VccB (see Top[2D])

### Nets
GND: C29.1 C30.1 R35.1 U4.7(~{OE}) U4.8(GND)
VccA: C29.2 R34.2 U4.14(VccA) ; port VccA
A1: U4.1(A1) ; port A1
A2: U4.2(A2) ; port A2
A3: U4.3(A3) ; port A3
A4: U4.4(A4) ; port A4
B1: U4.12(B1) ; port B1
B2: U4.11(B2) ; port B2
B3: U4.10(B3) ; port B3
B4: U4.9(B4) ; port B4
DIR: R34.1 R35.2 U4.5(DIR3) U4.6(DIR4) U4.15(DIR1) U4.16(DIR2) ; port DIR
VccB: C30.2 U4.13(VccB) ; port VccB

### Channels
LS: designators end in _LS4; ports A1=SDIO_0_2_L A2=SDIO_1_2_L A3=SDIO_2_2_L A4=SDIO_3_2_L B1=SDIO_0_2 B2=SDIO_1_2 B3=SDIO_2_2 B4=SDIO_3_2 DIR=DIR VccA=VccA VccB=VccB
LS: designators end in _LS3; ports A1=SDIO_0_L A2=SDIO_1_L A3=SDIO_2_L A4=SDIO_3_L B1=SDIO_0 B2=SDIO_1 B3=SDIO_2 B4=SDIO_3 DIR=DIR VccA=VccA VccB=VccB
LS: designators end in _LS2; ports A1=CSn_L A2=SCLK_L A3=IO_UPDATE_L A4=MASTER_RESET_L B1=CSn B2=SCLK B3=IO_UPDATE B4=MASTER_RESET DIR=DIR VccA=VccA VccB=VccB
LS: designators end in _LS1; ports A1=CSn_2_L A2=SCLK_2_L A3=IO_UPDATE_2_L A4=MASTER_RESET_2_L B1=CSn_2 B2=SCLK_2 B3=IO_UPDATE_2 B4=MASTER_RESET_2 DIR=DIR VccA=VccA VccB=VccB

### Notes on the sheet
- DIR=1 => A in =>B out
- Level Shifter
- 1.0
- Tal

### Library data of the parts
C29 C30 = CAP CER 6.8pF 50V NP0 0402: as C10 on sheet main
R34 = RES 3.09K OHM 1/16W 1% 0402: as R32 on sheet power
R35 = RES 3.09K OHM 1/16W 1% 0402: Manufacturer Part Number: RMCF0402FT3K09; Manufacturer: Stackpole Electronics Inc; Power (Watts): 0.063W, 1/16W; LANDA P/N: ERS-000063

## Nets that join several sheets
GND: Top (52 pins), M1 (39 pins), M1/A0 (29 pins), M1/A1 (29 pins), M1/B0 (29 pins), M1/B1 (29 pins), power (26 pins), M2 (39 pins), M2/A0 (29 pins), M2/A1 (29 pins), M2/B0 (29 pins), M2/B1 (29 pins), LS (5 pins), LS (5 pins), LS (5 pins), LS (5 pins)
P12V: Top (F3.1), power (6 pins)
VccA: Top (F2.2), M1 (6 pins), M1/A0 (C39_A2.2 C40_A2.2 U6_A2.1), M1/A1 (C39_A1.2 C40_A1.2 U6_A1.1), M1/B0 (C52_M1_B0.2 C53_M1_B0.2 U8_B2.1), M1/B1 (C52_M1_B1.2 C53_M1_B1.2 U8_B1.1), power (C24.2 FB5.2 R31.2 TP3.1), M2 (6 pins), M2/A0 (C39_A4.2 C40_A4.2 U6_A4.1), M2/A1 (C39_A3.2 C40_A3.2 U6_A3.1), M2/B0 (C52_B4.2 C53_B4.2 U8_B4.1), M2/B1 (C52_B3.2 C53_B3.2 U8_B3.1), LS (C29_LS4.2 R34_LS4.2 U4_LS4.14), LS (C29_LS3.2 R34_LS3.2 U4_LS3.14), LS (C29_LS2.2 R34_LS2.2 U4_LS2.14), LS (C29_LS1.2 R34_LS1.2 U4_LS1.14)
VccB: Top (F1.2), M1 (5 pins), M1/A0 (C37_A2.2 C38_A2.2 U5_A2.1), M1/A1 (C37_A1.2 C38_A1.2 U5_A1.1), M1/B0 (C50_M1_B0.2 C51_M1_B0.2 U7_B2.1), M1/B1 (C50_M1_B1.2 C51_M1_B1.2 U7_B1.1), power (C18.2 FB3.2 R28.2 TP2.1), M2 (5 pins), M2/A0 (C37_A4.2 C38_A4.2 U5_A4.1), M2/A1 (C37_A3.2 C38_A3.2 U5_A3.1), M2/B0 (C50_B4.2 C51_B4.2 U7_B4.1), M2/B1 (C50_B3.2 C51_B3.2 U7_B3.1), LS (C30_LS4.2 U4_LS4.13), LS (C30_LS3.2 U4_LS3.13), LS (C30_LS2.2 U4_LS2.13), LS (C30_LS1.2 U4_LS1.13)
AVDD: M1 (6 pins), M1/A1 (6 pins)
AVDD: M1 (R18_M1.2 R22_M1.2 R26_M1.2), M1/A0 (6 pins)
AVDD: M2 (6 pins), M2/A1 (6 pins)
AVDD: M2 (R18_M2.2 R22_M2.2 R26_M2.2), M2/A0 (6 pins)
CH_N: M1 (U1_M1.29), M1/A0 (R40_A2.2 T1_A2.3)
CH_N: M1 (U1_M1.35), M1/A1 (R40_A1.2 T1_A1.3)
CH_N: M2 (U1_M2.29), M2/A0 (R40_A4.2 T1_A4.3)
CH_N: M2 (U1_M2.35), M2/A1 (R40_A3.2 T1_A3.3)
CH_P: M1 (U1_M1.30), M1/A0 (R39_A2.1 T1_A2.1)
CH_P: M1 (U1_M1.36), M1/A1 (R39_A1.1 T1_A1.1)
CH_P: M2 (U1_M2.30), M2/A0 (R39_A4.1 T1_A4.1)
CH_P: M2 (U1_M2.36), M2/A1 (R39_A3.1 T1_A3.1)
contr0: Top (J2.25 J3.9 J6.A13), M2/A0 (U6_A4.2), M2/B0 (U8_B4.2)
contr0: Top (J2.26 J3.1 J6.B13), M1/A0 (U6_A2.2), M1/B0 (U8_B2.2)
contr1: Top (J2.27 J3.11 J6.A14), M2/A1 (U6_A3.2), M2/B1 (U8_B3.2)
contr1: Top (J2.28 J3.3 J6.B14), M1/A1 (U6_A1.2), M1/B1 (U8_B1.2)
CSn: M1 (U1_M1.47), LS (U4_LS2.12)
CSn_2: M2 (U1_M2.47), LS (U4_LS1.12)
CSn_2_L: Top (J2.7 J5.3 J6.A18), LS (U4_LS1.1)
CSn_L: Top (J2.8 J4.3 J6.B18), LS (U4_LS2.1)
DIR: Top (J2.21 J5.17 J6.A25), LS (6 pins), LS (6 pins)
DIR: Top (J2.22 J4.17 J6.B25), LS (6 pins), LS (6 pins)
IO_UPDATE: M1 (U1_M1.46), LS (U4_LS2.10)
IO_UPDATE_2: M2 (U1_M2.46), LS (U4_LS1.10)
IO_UPDATE_2_L: Top (J2.9 J5.1 J6.A19), LS (U4_LS1.3)
IO_UPDATE_L: Top (J2.10 J4.1 J6.B19), LS (U4_LS2.3)
MASTER_RESET_2_L: Top (J2.11 J5.7 J6.A20), LS (U4_LS1.4)
MASTER_RESET_L: Top (J2.12 J4.7 J6.B20), LS (U4_LS2.4)
SCLK: M1 (U1_M1.48), LS (U4_LS2.11)
SCLK_2: M2 (U1_M2.48), LS (U4_LS1.11)
SCLK_2_L: Top (J2.5 J5.5 J6.A17), LS (U4_LS1.2)
SCLK_L: Top (J2.6 J4.5 J6.B17), LS (U4_LS2.2)
SDIO_0: M1 (R3_M1.2 U1_M1.50), LS (U4_LS3.12)
SDIO_0_2: M2 (R3_M2.2 U1_M2.50), LS (U4_LS4.12)
SDIO_0_2_L: Top (J2.19 J5.15 J6.A24), LS (U4_LS4.1)
SDIO_0_L: Top (J2.20 J4.15 J6.B24), LS (U4_LS3.1)
SDIO_1: M1 (R4_M1.2 U1_M1.51), LS (U4_LS3.11)
SDIO_1_2: M2 (R4_M2.2 U1_M2.51), LS (U4_LS4.11)
SDIO_1_2_L: Top (J2.17 J5.13 J6.A23), LS (U4_LS4.2)
SDIO_1_L: Top (J2.18 J4.13 J6.B23), LS (U4_LS3.2)
SDIO_2: M1 (R5_M1.2 U1_M1.52), LS (U4_LS3.10)
SDIO_2_2: M2 (R5_M2.2 U1_M2.52), LS (U4_LS4.10)
SDIO_2_2_L: Top (J2.15 J5.11 J6.A22), LS (U4_LS4.3)
SDIO_2_L: Top (J2.16 J4.11 J6.B22), LS (U4_LS3.3)
SDIO_3: M1 (R6_M1.2 U1_M1.53), LS (U4_LS3.9)
SDIO_3_2: M2 (R6_M2.2 U1_M2.53), LS (U4_LS4.9)
SDIO_3_2_L: Top (J2.13 J5.9 J6.A21), LS (U4_LS4.4)
SDIO_3_L: Top (J2.14 J4.9 J6.B21), LS (U4_LS3.4)
SYNC_CLK: Top (J2.24 J4.19 J6.B26), M1 (U1_M1.54)
SYNC_CLK_2: Top (J2.23 J5.19 J6.A26), M2 (U1_M2.54)
SYNC_IN: Top (TP4.1), M1 (U1_M1.1)
SYNC_IN_2: Top (R33.1), M2 (U1_M2.1)
SYNC_OUT: Top (TP5.1), M2 (U1_M2.2)
SYNC_OUT: Top (R33.2), M1 (U1_M1.2)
